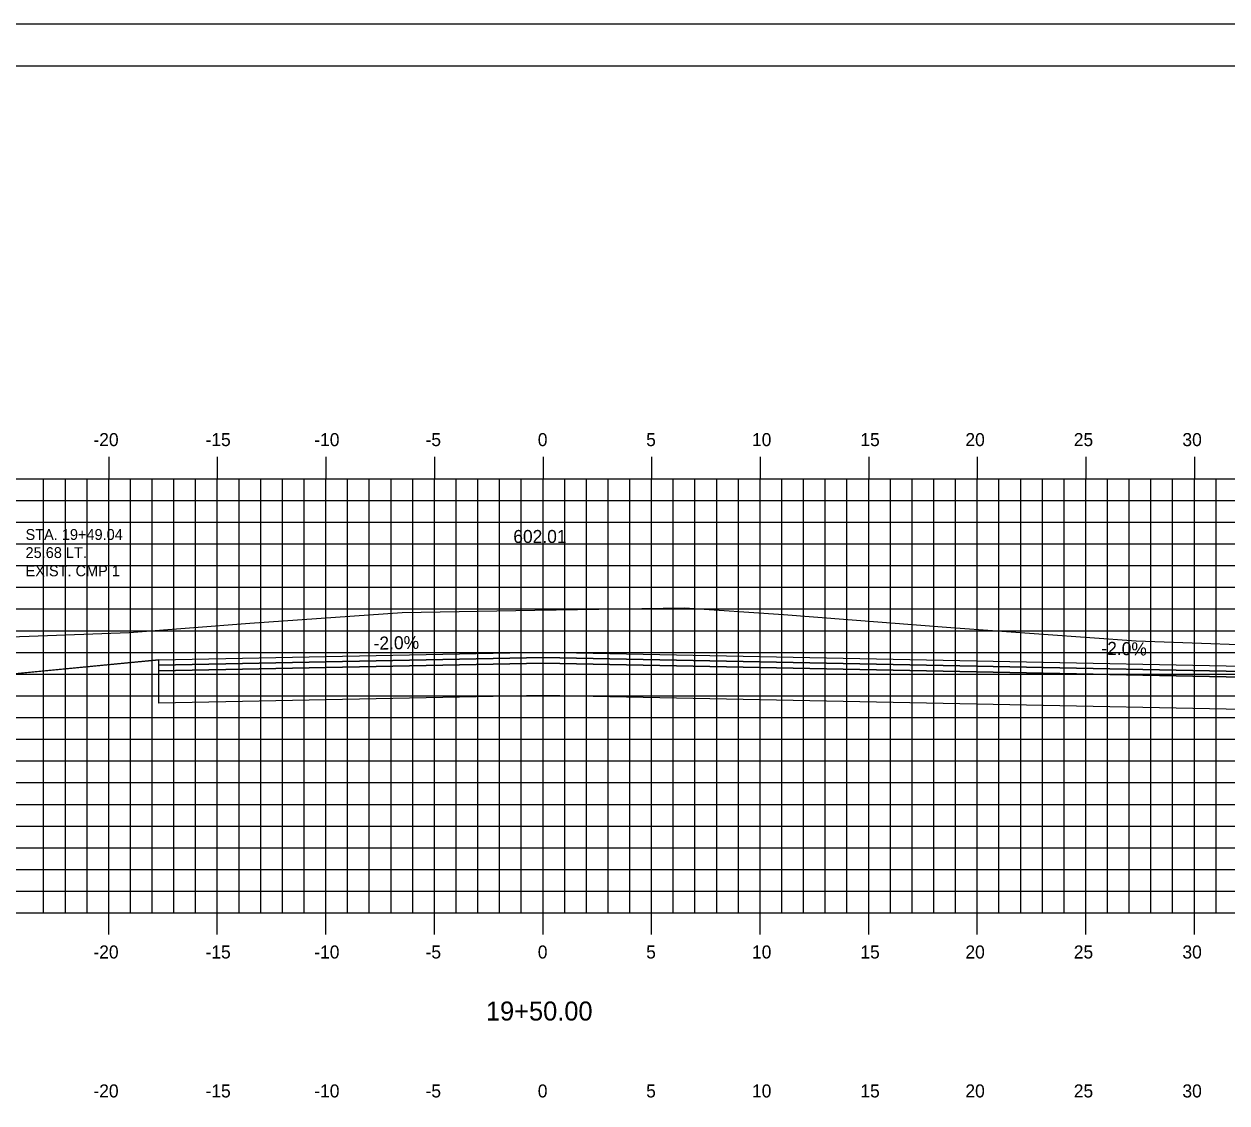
# Model space of a CAD drawing. Extents: x 1048141 to 1048311, y 780904 to 781014.
# Drawn here: x 1048199.8 to 1048255.2, y 780964.4 to 781014.1 of the extents above; entities that cross this region are included whole.
import ezdxf

# ---------------------------------------------------------------- set-up
doc = ezdxf.new("R2010")
doc.units = 0
for name, color, linetype in [('ANNOTATION', 7, 'Continuous'), ('D_Roadway_Centerline', 7, 'Continuous'), ('D_Roadway_Centerline_Text', 7, 'Continuous'), ('D_Roadway_Edge_Pavement', 7, 'Continuous'), ('D_Roadway_Pavement', 7, 'Continuous'), ('D_Roadway_SlopeLines', 7, 'Continuous'), ('D_Roadway_SubGrade', 7, 'Continuous'), ('D_Text_Monospaced', 7, 'Continuous'), ('Default', 7, 'Continuous'), ('H_V ANNOTATION', 7, 'Continuous'), ('MAJOR', 7, 'Continuous'), ('MINOR', 7, 'Continuous'), ('S_Roadway_Centerline', 7, 'Continuous')]:
    doc.layers.add(name, color=color, linetype=linetype)

msp = doc.modelspace()

# ---------------------------------------------------------------- linework, layer by layer
at = {"layer": 'D_Roadway_Centerline'}
msp.add_lwpolyline([(1048168.417, 780981.167), (1048206.016, 780984.768), (1048223.713, 780985.121), (1048277.445, 780984.047), (1048282.445, 780983.218)], dxfattribs=at)
at = {"layer": 'D_Roadway_Edge_Pavement'}
msp.add_lwpolyline([(1048206.016, 780984.518), (1048206.016, 780984.768), (1048223.713, 780985.121), (1048277.445, 780984.047), (1048277.445, 780983.797), (1048223.713, 780984.871)], close=True, dxfattribs=at)
at = {"layer": 'D_Roadway_Pavement'}
msp.add_lwpolyline([(1048206.016, 780984.268), (1048206.016, 780984.518), (1048223.713, 780984.871), (1048277.445, 780983.797), (1048277.445, 780983.547), (1048223.713, 780984.621)], close=True, dxfattribs=at)
at = {"layer": 'D_Roadway_SlopeLines'}
msp.add_line((1048206.016, 780984.768), (1048168.417, 780981.167), dxfattribs=at)
at = {"layer": 'D_Roadway_SubGrade'}
msp.add_lwpolyline([(1048206.016, 780982.768), (1048206.016, 780984.268), (1048223.713, 780984.621), (1048277.445, 780983.547), (1048277.445, 780982.047), (1048223.713, 780983.121)], close=True, dxfattribs=at)
at = {"layer": 'Default'}
msp.add_line((1048308.713, 781012.114), (1048148.713, 781012.114), dxfattribs=at)
msp.add_lwpolyline([(1048140.62, 780904.055), (1048310.62, 780904.055), (1048310.62, 781014.055), (1048140.62, 781014.055)], close=True, dxfattribs=at)
at = {"layer": 'MAJOR'}
for p, q in [((1048203.713, 780994.116), (1048203.713, 780993.114)), ((1048208.713, 780994.116), (1048208.713, 780993.114)), ((1048213.713, 780994.116), (1048213.713, 780993.114)), ((1048218.713, 780994.116), (1048218.713, 780993.114)), ((1048223.713, 780994.116), (1048223.713, 780993.114)), ((1048228.713, 780994.116), (1048228.713, 780993.114)), ((1048233.713, 780994.116), (1048233.713, 780993.114)), ((1048238.713, 780994.116), (1048238.713, 780993.114)), ((1048243.713, 780994.116), (1048243.713, 780993.114)), ((1048248.713, 780994.116), (1048248.713, 780993.114)), ((1048253.713, 780994.116), (1048253.713, 780993.114)), ((1048153.713, 780993.114), (1048293.713, 780993.114)), ((1048153.713, 780993.114), (1048293.713, 780993.114)), ((1048203.713, 780973.114), (1048203.713, 780993.114)), ((1048208.713, 780973.114), (1048208.713, 780993.114)), ((1048213.713, 780973.114), (1048213.713, 780993.114)), ((1048218.713, 780973.114), (1048218.713, 780993.114)), ((1048223.713, 780973.114), (1048223.713, 780993.114)), ((1048228.713, 780973.114), (1048228.713, 780993.114)), ((1048233.713, 780973.114), (1048233.713, 780993.114)), ((1048238.713, 780973.114), (1048238.713, 780993.114)), ((1048243.713, 780973.114), (1048243.713, 780993.114)), ((1048248.713, 780973.114), (1048248.713, 780993.114)), ((1048253.713, 780973.114), (1048253.713, 780993.114)), ((1048153.713, 780988.114), (1048293.713, 780988.114)), ((1048153.713, 780983.114), (1048293.713, 780983.114)), ((1048153.713, 780978.114), (1048293.713, 780978.114)), ((1048153.713, 780973.114), (1048293.713, 780973.114)), ((1048153.713, 780973.114), (1048293.713, 780973.114)), ((1048203.713, 780972.112), (1048203.713, 780973.114)), ((1048208.713, 780972.112), (1048208.713, 780973.114)), ((1048213.713, 780972.112), (1048213.713, 780973.114)), ((1048218.713, 780972.112), (1048218.713, 780973.114)), ((1048223.713, 780972.112), (1048223.713, 780973.114)), ((1048228.713, 780972.112), (1048228.713, 780973.114)), ((1048233.713, 780972.112), (1048233.713, 780973.114)), ((1048238.713, 780972.112), (1048238.713, 780973.114)), ((1048243.713, 780972.112), (1048243.713, 780973.114)), ((1048248.713, 780972.112), (1048248.713, 780973.114)), ((1048253.713, 780972.112), (1048253.713, 780973.114))]:
    msp.add_line(p, q, dxfattribs=at)
at = {"layer": 'MINOR'}
for p, q in [((1048200.713, 780973.114), (1048200.713, 780993.114)), ((1048201.713, 780973.114), (1048201.713, 780993.114)), ((1048202.713, 780973.114), (1048202.713, 780993.114)), ((1048204.713, 780973.114), (1048204.713, 780993.114)), ((1048205.713, 780973.114), (1048205.713, 780993.114)), ((1048206.713, 780973.114), (1048206.713, 780993.114)), ((1048207.713, 780973.114), (1048207.713, 780993.114)), ((1048209.713, 780973.114), (1048209.713, 780993.114)), ((1048210.713, 780973.114), (1048210.713, 780993.114)), ((1048211.713, 780973.114), (1048211.713, 780993.114)), ((1048212.713, 780973.114), (1048212.713, 780993.114)), ((1048214.713, 780973.114), (1048214.713, 780993.114)), ((1048215.713, 780973.114), (1048215.713, 780993.114)), ((1048216.713, 780973.114), (1048216.713, 780993.114)), ((1048217.713, 780973.114), (1048217.713, 780993.114)), ((1048219.713, 780973.114), (1048219.713, 780993.114)), ((1048220.713, 780973.114), (1048220.713, 780993.114)), ((1048221.713, 780973.114), (1048221.713, 780993.114)), ((1048222.713, 780973.114), (1048222.713, 780993.114)), ((1048224.713, 780973.114), (1048224.713, 780993.114)), ((1048225.713, 780973.114), (1048225.713, 780993.114)), ((1048226.713, 780973.114), (1048226.713, 780993.114)), ((1048227.713, 780973.114), (1048227.713, 780993.114)), ((1048229.713, 780973.114), (1048229.713, 780993.114)), ((1048230.713, 780973.114), (1048230.713, 780993.114)), ((1048231.713, 780973.114), (1048231.713, 780993.114)), ((1048232.713, 780973.114), (1048232.713, 780993.114)), ((1048234.713, 780973.114), (1048234.713, 780993.114)), ((1048235.713, 780973.114), (1048235.713, 780993.114)), ((1048236.713, 780973.114), (1048236.713, 780993.114)), ((1048237.713, 780973.114), (1048237.713, 780993.114)), ((1048239.713, 780973.114), (1048239.713, 780993.114)), ((1048240.713, 780973.114), (1048240.713, 780993.114)), ((1048241.713, 780973.114), (1048241.713, 780993.114)), ((1048242.713, 780973.114), (1048242.713, 780993.114)), ((1048244.713, 780973.114), (1048244.713, 780993.114)), ((1048245.713, 780973.114), (1048245.713, 780993.114)), ((1048246.713, 780973.114), (1048246.713, 780993.114)), ((1048247.713, 780973.114), (1048247.713, 780993.114)), ((1048249.713, 780973.114), (1048249.713, 780993.114)), ((1048250.713, 780973.114), (1048250.713, 780993.114)), ((1048251.713, 780973.114), (1048251.713, 780993.114)), ((1048252.713, 780973.114), (1048252.713, 780993.114)), ((1048254.713, 780973.114), (1048254.713, 780993.114)), ((1048153.713, 780992.114), (1048293.713, 780992.114)), ((1048153.713, 780991.114), (1048293.713, 780991.114)), ((1048153.713, 780990.114), (1048293.713, 780990.114)), ((1048153.713, 780989.114), (1048293.713, 780989.114)), ((1048153.713, 780987.114), (1048293.713, 780987.114)), ((1048153.713, 780986.114), (1048293.713, 780986.114)), ((1048153.713, 780985.114), (1048293.713, 780985.114)), ((1048153.713, 780984.114), (1048293.713, 780984.114)), ((1048153.713, 780982.114), (1048293.713, 780982.114)), ((1048153.713, 780981.114), (1048293.713, 780981.114)), ((1048153.713, 780980.114), (1048293.713, 780980.114)), ((1048153.713, 780979.114), (1048293.713, 780979.114)), ((1048153.713, 780977.114), (1048293.713, 780977.114)), ((1048153.713, 780976.114), (1048293.713, 780976.114)), ((1048153.713, 780975.114), (1048293.713, 780975.114)), ((1048153.713, 780974.114), (1048293.713, 780974.114))]:
    msp.add_line(p, q, dxfattribs=at)
at = {"layer": 'S_Roadway_Centerline'}
msp.add_lwpolyline([(1048196.003, 780985.718), (1048200.047, 780985.855), (1048204.657, 780986.031), (1048210.211, 780986.463), (1048217.23, 780986.949), (1048223.338, 780987.063), (1048230.229, 780987.172), (1048234.784, 780986.855), (1048242.494, 780986.262), (1048251.037, 780985.64), (1048258.754, 780985.363), (1048262.181, 780985.235), (1048264.072, 780985.322), (1048264.692, 780985.389), (1048266.688, 780985.402), (1048279.313, 780983.59), (1048279.814, 780983.509), (1048280.017, 780983.484), (1048280.104, 780983.476), (1048280.174, 780983.466), (1048280.269, 780983.46), (1048282.226, 780983.239), (1048293.713, 780982.125)], dxfattribs=at)

# ---------------------------------------------------------------- texts
at = {"layer": 'ANNOTATION'}
for rotation, p in [(1.1458, (1048215.916, 780985.234)), (358.8542, (1048249.422, 780985.008))]:
    msp.add_text('-2.0%', height=0.6, rotation=rotation, dxfattribs=at).set_placement(p)
at = {"layer": 'D_Roadway_Centerline_Text'}
msp.add_text('602.01', height=0.6, dxfattribs=at).set_placement((1048222.343, 780990.153))
at = {"layer": 'D_Text_Monospaced'}
for s, height, p in [('STA. 19+49.04', 0.49998, (1048199.88, 780990.294)), ('25.68 LT.', 0.5, (1048199.88, 780989.46)), ('EXIST. CMP 1', 0.49998, (1048199.88, 780988.62))]:
    msp.add_text(s, height=height, dxfattribs=at).set_placement(p)
at = {"layer": 'H_V ANNOTATION'}
for s, height, p in [('-20', 0.6, (1048203.006, 780994.614)), ('-15', 0.6, (1048208.17, 780994.614)), ('-10', 0.6, (1048213.178, 780994.614)), ('-5', 0.6, (1048218.303, 780994.614)), ('0', 0.6, (1048223.472, 780994.614)), ('5', 0.6, (1048228.464, 780994.614)), ('10', 0.6, (1048233.338, 780994.614)), ('15', 0.6, (1048238.33, 780994.614)), ('20', 0.6, (1048243.167, 780994.614)), ('25', 0.6, (1048248.159, 780994.614)), ('30', 0.6, (1048253.162, 780994.614)), ('-20', 0.6, (1048203.006, 780971.014)), ('-15', 0.6, (1048208.17, 780971.014)), ('-10', 0.6, (1048213.178, 780971.014)), ('-5', 0.6, (1048218.303, 780971.014)), ('0', 0.6, (1048223.472, 780971.014)), ('5', 0.6, (1048228.464, 780971.014)), ('10', 0.6, (1048233.338, 780971.014)), ('15', 0.6, (1048238.33, 780971.014)), ('20', 0.6, (1048243.167, 780971.014)), ('25', 0.6, (1048248.159, 780971.014)), ('30', 0.6, (1048253.162, 780971.014)), ('19+50.00', 0.875, (1048221.083, 780968.157)), ('-20', 0.6, (1048203.006, 780964.614)), ('-15', 0.6, (1048208.17, 780964.614)), ('-10', 0.6, (1048213.178, 780964.614)), ('-5', 0.6, (1048218.303, 780964.614)), ('0', 0.6, (1048223.472, 780964.614)), ('5', 0.6, (1048228.464, 780964.614)), ('10', 0.6, (1048233.338, 780964.614)), ('15', 0.6, (1048238.33, 780964.614)), ('20', 0.6, (1048243.167, 780964.614)), ('25', 0.6, (1048248.159, 780964.614)), ('30', 0.6, (1048253.162, 780964.614))]:
    msp.add_text(s, height=height, dxfattribs=at).set_placement(p)
at = {"layer": 'S_Roadway_Centerline'}
for s, p in [('L', (1048217.222, 780986.942)), ('C', (1048217.225, 780986.949))]:
    msp.add_text(s, height=0.0146, dxfattribs=at).set_placement(p)

doc.saveas('drawing.dxf')
